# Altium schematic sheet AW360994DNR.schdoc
size 127 x 101 mm
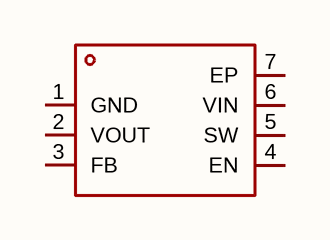
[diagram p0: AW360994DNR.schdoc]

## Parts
U?  aw360994dnr  [TDFN-6_L2.0-W2.0-P0.65-BL-EP]  (value not drawn)

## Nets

Not connected (* = marked no-connect by the designer): U? 1(GND) 2(VOUT) 3(FB) 4(EN) 5(SW) 6(VIN) 7(EP)

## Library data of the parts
U? = aw360994dnr: 功能类型:升压型;工作电压:800mV~5.2V;输出电压:3.3V;输出电流:600mA;输出类型:固定;; Manufacturer: AWINIC(艾为); AddInBom: yes; ModelId: cf7eaf10a6c84f09add415985fbe5dc3; ModelName: TDFN-6_L2.0-W2.0-H0.8-P0.65; ModelTransform: 79.527,78.74,0,90,0,0,0,0.0005,0; Function: 升压型; Output Voltage: 3.3V; Output Current: 600mA; Synchronous Rectifier: 是; Number of Outputs: 1; Topology: 升压式; Quiescent Current: 350nA; Switch tube (built-in/external): 内置; Output Type: 固定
